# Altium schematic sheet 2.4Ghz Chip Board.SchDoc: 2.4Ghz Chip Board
size Letter
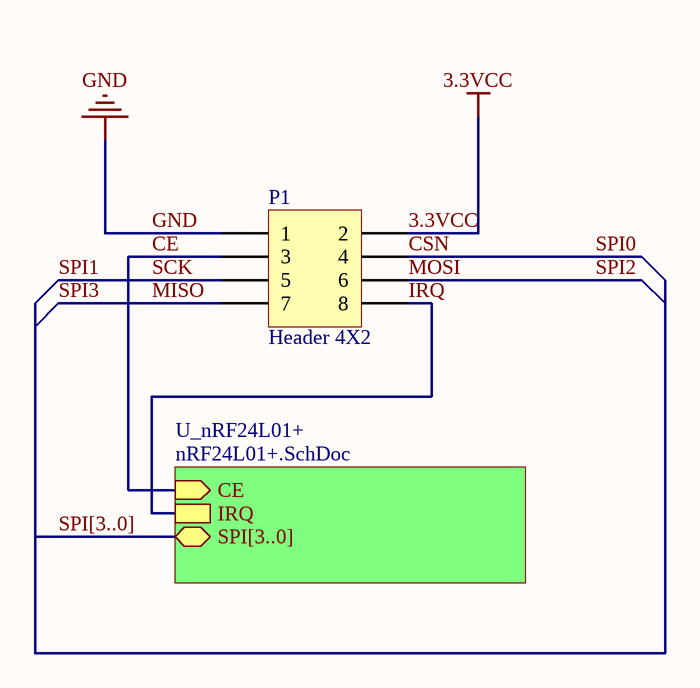
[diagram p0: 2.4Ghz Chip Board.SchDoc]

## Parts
P1  Header 4X2  [HDR2X4]

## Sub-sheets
U_nRF24L01+ = nRF24L01+.SchDoc: CE (in), IRQ, SPI[3..0] (bidir)

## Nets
3.3VCC: P1.2
GND: P1.1
CE: P1.3 ; sheet U_nRF24L01+/CE
CSN: P1.4  [also labelled SPI0]
IRQ: P1.8 ; sheet U_nRF24L01+/IRQ
MISO: P1.7  [also labelled SPI3]
MOSI: P1.6  [also labelled SPI2]
SCK: P1.5  [also labelled SPI1]

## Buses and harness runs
bus SPI[3..0] = sheet U_nRF24L01+/SPI[3..0]

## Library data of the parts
P1 = Header 4X2: Header, 4-Pin, Dual row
